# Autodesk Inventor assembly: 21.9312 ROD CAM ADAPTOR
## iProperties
Created: 2007-03
Part Number: 21.9312 ROD CAM ADAPTOR
Document SubType Name: Assembly
Designer: Andy Moles
Translation Standard: STEP AP214IS
File Name: 1000-U49_ASM
Preprocessor: PRO/ENGINEER BY PARAMETRIC TECHNOLOGY CORPORATION, 2005310
Postprocessor: Build: 344b, Release: 11 SP2 - Date: Fri 08/18/2006
Sent Units: MILLIMETERS
Uncertainty: 0.004211719462213
Author: Andy Moles
